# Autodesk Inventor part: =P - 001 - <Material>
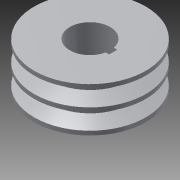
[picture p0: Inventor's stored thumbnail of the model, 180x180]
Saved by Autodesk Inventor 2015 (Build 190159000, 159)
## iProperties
Created: 2007-02
Part Number: =P - 001 - <Material>
Material: Aluminum-6061
Document SubType Name: Modeling
Designer: Autodesk, Inc.
Density: 2.71 g/cm^3
Mass: 355.844 g
Surface Area: 306.648 cm^2
Volume: 131.308 cm^3
Description: =Pulley - <Mass>
Appearance: Aluminum - Flat
CustomPartVersion: 1
Author: Autodesk, Inc.
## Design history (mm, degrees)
sketch "Main Sketch"
  geometry: L1 (0, 34.925)-(43.815, 34.925); L2 (43.815, 34.925)-(43.815, 15.804); L3 (43.815, 15.804)-(32.131, 12.232); L4 (32.131, 12.232)-(32.131, 6.818); L5 (32.131, 6.818)-(43.815, 3.246); L6 (43.815, 3.246)-(43.815, 0); L7 (43.815, 0)-(0, 0); L8 (40.64, 14.834)-(40.64, 4.216); L9 (0, 34.925)-(0, 0); L10 (32.131, 9.525)-(40.64, 9.525); L11 (43.815, 15.804)-(43.815, 3.246); L12 (0, -6.985)-(0, 41.91) reference
  constraints: 22 end point, 5 perpendicular, 3 collinear, 2 midpoint, 2 point on line, 1 parallel
  dimensions: "d0" = 10.6172 distance of L8.start L8.end (= da_Bw); "d1" = 34 deg angle of L3 L5 (= da_Alfa); "d2" = 3.175 distance between parallel lines of L2 L8 (= da_c); "d6" = 34.925 distance between parallel lines of L7 L1 (computed from d5, da_ng, da_Sg); "d21" = 81.28 diameter of L8 L12 (= da_Dw); "d25" = 11.684 distance between parallel lines of L4 L11 (= da_Hd); "d27" = 9.525 distance between parallel lines of L7 L10 (= da_Se)
node "Belt Plane"
revolve "Body" stored, may be unused: angle "d7" = 90 deg
revolve "Groove" stored, may be unused: angle "d15" = 90 deg
fillet "Fillet External" dims "d8" = 0 (computed from da_r1), "d10" = 0, "da_r1" = 0 [user parameter; used in 1 equation term]
fillet "Fillet Internal" dims "d9" = 0 (computed from da_r2), "d11" = 0, "da_r2" = 0 [user parameter; used in 1 equation term]
pattern_linear "Groove Pattern" dims "d18" = 15.875 (= da_Sg)
feature "Hub Keyway"
body "Solid1"
other parameters: "d5" = 9.525 (= da_Se), "da_Bw" = 10.6172 [user parameter; used in 1 equation term], "da_Alfa" = 34 deg [user parameter; used in 1 equation term], "da_c" = 3.175 [user parameter; used in 1 equation term], "da_Dw" = 81.28 [user parameter; used in 1 equation term], "da_Hd" = 11.684 [user parameter; used in 1 equation term], "da_Se" = 9.525 [user parameter; used in 2 equation terms], "da_Sg" = 15.875 [user parameter; used in 2 equation terms], "d24" = 0, "d26" = 0
